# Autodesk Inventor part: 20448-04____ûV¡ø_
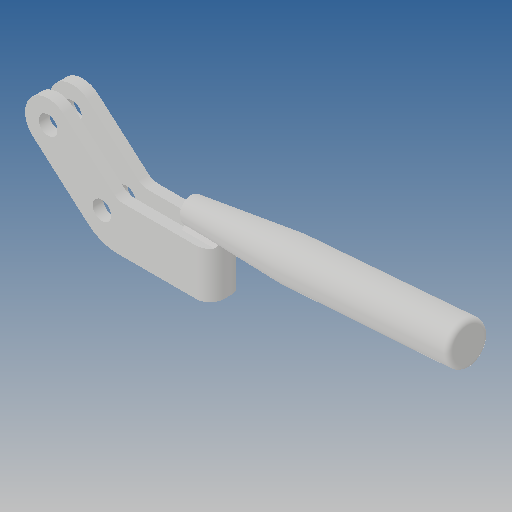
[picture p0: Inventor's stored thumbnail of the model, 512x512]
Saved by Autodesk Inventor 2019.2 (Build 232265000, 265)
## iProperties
Created: 2010-06
Part Number: 20448-04____ûV¡ø_
Material: Ogólny
Document SubType Name: Modeling
Designer: CADENGINEERING4
Density: 1 g/cm^3
Appearance: Domyślna
Author: CADENGINEERING4
Revision Number: ANY
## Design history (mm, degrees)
feature "NONE"
feature "NONE:1"
feature "NONE:2"
feature "NONE:3"
feature "NONE:4"
node "Bryła1"
node "Bryła2"
node "Bryła3"
node "Bryła4"
node "Bryła5"
